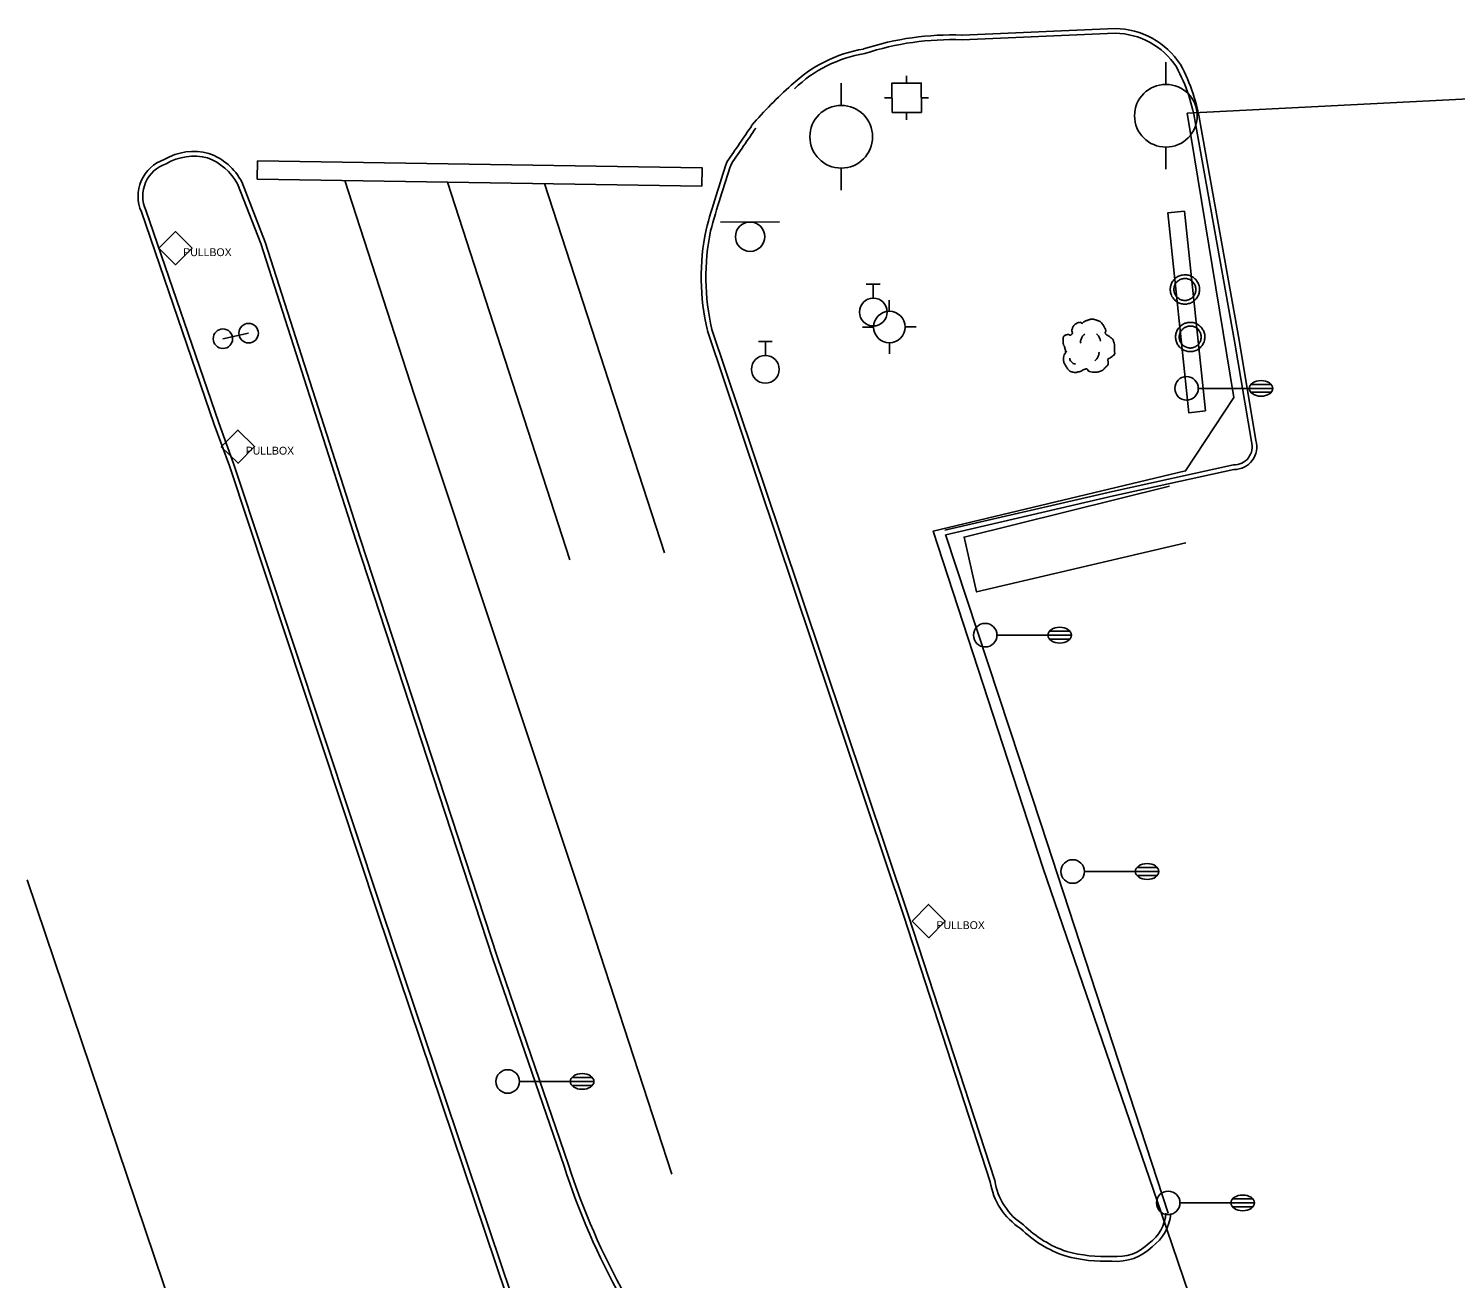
# Model space of a CAD drawing. Extents: x 2145380 to 2156929, y 139568 to 149130.
# Drawn here: x 2147379.3 to 2147561.3, y 142759 to 142918.4 of the extents above; entities that cross this region are included whole.
import ezdxf

# ---------------------------------------------------------------- set-up
doc = ezdxf.new("R2010")
doc.units = 0
for name, color, linetype in [('Default', 7, 'Continuous'), ('TOPO_Asphalt', 7, 'Continuous'), ('TOPO_Curb Back', 7, 'Continuous'), ('TOPO_Fence', 7, 'Continuous'), ('TOPO_Guardrail', 7, 'Continuous'), ('TOPO_Light Pole', 7, 'Continuous'), ('TOPO_Misc', 7, 'Continuous'), ('TOPO_Misc Line', 7, 'Continuous'), ('TOPO_Power Pole', 7, 'Continuous'), ('TOPO_Power Pullbox', 7, 'Continuous'), ('TOPO_Sign', 7, 'Continuous'), ('TOPO_Traffic Signal', 7, 'Continuous'), ('TOPO_Tree', 7, 'Continuous'), ('TOPO_Wall Freestanding', 7, 'Continuous'), ('TOPO_Water Fire Hydrant', 7, 'Continuous'), ('TOPO_Water Valve', 7, 'Continuous')]:
    doc.layers.add(name, color=color, linetype=linetype)

# ---------------------------------------------------------------- blocks, each defined once
blk = doc.blocks.new('POST')
at = {"layer": 'TOPO_Misc'}
for start, end in [(90, 180), (180, 270), (360, 90), (270, 0)]:
    blk.add_arc((-0.01, 0.03), 3.16, start, end, dxfattribs=at)
blk = doc.blocks.new('LP')
at = {"layer": 'TOPO_Light Pole'}
blk.add_line((3.81, 0), (20.32, 0), dxfattribs=at)
for points in [[(20.32, 0), (27.94, 0)], [(20.32, 0), (23.5, 0)], [(20.83, 1.27), (27.43, 1.27)], [(20.83, 1.27), (23.5, 1.27)], [(23.71, 1.27), (27.43, 1.27)], [(23.71, 0), (27.94, 0)], [(20.83, -1.27), (27.43, -1.27)], [(20.83, -1.27), (23.5, -1.27)], [(23.71, -1.27), (27.43, -1.27)]]:
    blk.add_lwpolyline(points, dxfattribs=at)
blk.add_circle((0, 0), 3.81, dxfattribs=at)
blk.add_ellipse((24.13, 0), major_axis=(3.81, 0), ratio=0.666667, dxfattribs=at)
blk = doc.blocks.new('FIRHYD')
at = {"layer": 'TOPO_Water Fire Hydrant'}
for p, q in [((-0.02, 10.16), (-0.03, 17.34)), ((10.16, 0.02), (17.34, 0.03)), ((-10.16, -0.02), (-17.34, -0.03)), ((0.02, -10.16), (0.03, -17.34))]:
    blk.add_line(p, q, dxfattribs=at)
blk.add_circle((0, 0), 10.16, dxfattribs=at)
blk = doc.blocks.new('TRFSIG')
at = {"layer": 'TOPO_Traffic Signal'}
for p, q in [((0.04, 4.66), (0.04, 7.04)), ((-4.7, -0.09), (-7.08, -0.09)), ((4.79, -0.09), (7.17, -0.09)), ((0.04, -4.83), (0.04, -7.22))]:
    blk.add_line(p, q, dxfattribs=at)
blk.add_lwpolyline([(-4.7, -4.85), (4.81, -4.83), (4.79, 4.67), (-4.72, 4.66), (-4.7, -4.85)], dxfattribs=at)
blk = doc.blocks.new('TREE')
at = {"layer": 'TOPO_Tree'}
for points in [[(-14.07, -0.4), (-14.17, 0.5), (-14.37, 1.38), (-14.6, 2.25), (-14.84, 3.17), (-15.47, 3.96), (-15.66, 4.9), (-15.8, 5.59), (-15.71, 6.31), (-15.66, 7.01), (-15.6, 7.91), (-15.72, 8.8), (-15.13, 9.66), (-14.62, 10.42), (-13.76, 10.49), (-13.02, 10.72), (-12.18, 10.98), (-11.06, 10), (-10.37, 10.72), (-9.4, 11.74), (-10.29, 13.28), (-9.84, 14.42), (-9.56, 15.15), (-9.32, 15.89), (-8.78, 16.54), (-8.18, 17.26), (-7.5, 17.68), (-6.67, 18.13), (-6.14, 18.41), (-5.61, 18.61), (-5.08, 18.66), (-4.55, 18.71), (-4.02, 18.54), (-3.49, 18.13)], [(-3.49, 17.6), (-3.07, 18.27), (-2.58, 18.8), (-1.9, 19.19), (-1.05, 19.68), (-0.19, 19.96), (0.74, 20.24), (1.62, 20.51), (2.51, 20.82), (3.39, 20.77), (4.1, 20.73), (4.8, 20.47), (5.51, 20.24), (6.43, 19.95), (7.32, 19.73), (8.15, 19.19), (9.36, 18.4), (10.02, 17.21), (10.8, 16.01), (11.24, 15.33), (11.58, 14.62), (11.86, 13.89), (12.17, 13.08), (11.37, 12.02), (11.86, 11.25), (12, 11.03), (12.18, 10.86), (12.39, 10.72), (12.91, 10.35), (13.45, 10.02), (13.97, 9.66), (14.7, 9.16), (15.41, 8.68), (16.09, 8.07), (16.7, 7.53), (16.93, 6.73), (17.15, 5.95), (17.59, 4.38), (17.71, 2.77), (17.68, 1.19), (17.65, -0.25), (17.83, -2.22), (16.62, -3.04), (15.47, -3.83), (14.31, -4.58), (13.16, -5.35)], [(-4.21, 5.09), (-4.46, 6.09), (-4.3, 7.21), (-3.84, 8.21), (-3.33, 9.34), (-2.71, 10.27), (-1.64, 10.97)], [(5.89, 11.15), (6.5, 10.68), (6.96, 10.17), (7.36, 9.5), (7.93, 8.56), (8.31, 7.6), (8.46, 6.56)], [(13.16, -5.34), (13.25, -5.81), (13.36, -6.28), (13.45, -6.75), (13.76, -8.52), (12.24, -10.03), (10.8, -11.51), (9.98, -12.34), (9.13, -12.77), (8.15, -13.1), (5.97, -13.83), (3.32, -13.56), (1.27, -13.1), (0.49, -12.92), (-0.06, -11.44), (-0.84, -11.51), (-2.04, -11.61), (-3.28, -12.78), (-4.55, -13.1), (-6.06, -13.47), (-7.77, -14.03), (-9.31, -13.62), (-11.36, -13.09), (-12.84, -11.41), (-14.07, -9.39), (-15.32, -7.35), (-15.61, -5.13), (-15.13, -3.04), (-14.87, -1.89), (-13.91, -0.75), (-13.54, 0.13)], [(-11.38, -4.46), (-11.47, -5.41), (-11.03, -6.32), (-10.09, -7.22), (-9.3, -7.97), (-8.49, -8.26), (-7.7, -8.14)], [(4.79, -6.29), (5.71, -5.66), (6.3, -4.92), (6.81, -3.91), (7.36, -2.81), (7.63, -1.7), (7.54, -0.6)]]:
    blk.add_open_spline(points, degree=3, dxfattribs=at)
blk = doc.blocks.new('pulbox')
at = {"layer": 'Default'}
blk.add_lwpolyline([(-5.38, -0.01), (-0.02, 5.42), (5.4, 0.06), (0.05, -5.36), (-5.38, -0.01)], dxfattribs=at)
blk.add_text('PULLBOX', height=2.54, dxfattribs=at).set_placement((2.54, -2.54))
blk = doc.blocks.new('POWPOL')
at = {"layer": 'TOPO_Power Pole'}
for p, q in [((0, 10.16), (0, 17.34)), ((0, -10.16), (0, -17.34))]:
    blk.add_line(p, q, dxfattribs=at)
blk.add_circle((0, 0), 10.16, dxfattribs=at)
blk = doc.blocks.new('WATVAL')
at = {"layer": 'Default'}
for p, q in [((-2.25, 9), (2.25, 9)), ((0, 4.5), (0, 9))]:
    blk.add_line(p, q, dxfattribs=at)
blk.add_circle((0, 0), 4.5, dxfattribs=at)

msp = doc.modelspace()

# ---------------------------------------------------------------- linework, layer by layer
at = {"layer": 'TOPO_Asphalt'}
msp.add_line((2147379.12, 142809.78), (2147402.56, 142740.4), dxfattribs=at)
msp.add_lwpolyline([(2147496.3, 142853.83), (2147508.5, 142816.84), (2147524.71, 142767.27)], dxfattribs=at)
msp.add_arc((2147509.82, 142873.43), 50.24, 131.3733, 139.5513, dxfattribs=at)
at = {"layer": 'TOPO_Curb Back'}
for points in [[(2147498.39, 142917.52), (2147517.93, 142918.36)], [(2147498.39, 142916.92), (2147517.94, 142917.76)], [(2147528.21, 142905.99), (2147533.14, 142878.51), (2147535.31, 142865.7)], [(2147528.81, 142906.09), (2147533.73, 142878.61), (2147535.89, 142865.84)], [(2147405.97, 142898.56), (2147408.92, 142890.94), (2147421.05, 142853.12), (2147438.54, 142799.71), (2147447.62, 142773.28)], [(2147406.51, 142898.82), (2147409.49, 142891.14), (2147421.62, 142853.31), (2147439.11, 142799.9), (2147448.19, 142773.47)], [(2147459.61, 142697.37), (2147440.29, 142756.78), (2147423.84, 142805.62), (2147404.95, 142862.58), (2147403, 142867.87), (2147393.71, 142894.97)], [(2147460.18, 142697.55), (2147440.86, 142756.97), (2147424.41, 142805.81), (2147405.51, 142862.78), (2147403.56, 142868.07), (2147394.27, 142895.2)], [(2147501.98, 142771.3), (2147490.97, 142805.16), (2147474.68, 142853.73), (2147465.91, 142879.83)], [(2147502.56, 142771.44), (2147491.54, 142805.34), (2147475.25, 142853.92), (2147466.49, 142880)], [(2147533.02, 142862.74), (2147517.6, 142859.34), (2147496.18, 142854.4)], [(2147533.08, 142862.14), (2147517.73, 142858.75), (2147496.31, 142853.81)]]:
    msp.add_lwpolyline(points, dxfattribs=at)
for centre, radius, start, end in [((2147497.1, 142881.19), 36.36, 87.9692, 108.0515), ((2147497.1, 142881.19), 35.76, 87.9317, 108.1243), ((2147517.85, 142908.37), 9.99, 32.7044, 89.5788), ((2147517.85, 142908.37), 9.39, 32.8416, 89.4881), ((2147488.7, 142898.54), 17.45, 99.439, 133.8316), ((2147488.7, 142898.54), 16.85, 99.2861, 133.8316), ((2147505.88, 142902.76), 22.57, 8.2439, 28.3156), ((2147505.88, 142902.76), 23.17, 8.2689, 28.3737), ((2146881.44, 143306.93), 713.45, 325.36065, 325.80896), ((2146881.44, 143306.93), 714.05, 325.36729, 325.80896), ((2147400.38, 142895.27), 7.42, 74.9444, 120.5515), ((2147399.61, 142895.05), 7.87, 28.6108, 69.8923), ((2147398.21, 142896.99), 4.94, 108.9166, 204.1165), ((2147398.21, 142896.99), 4.34, 108.1176, 204.4649), ((2147400.38, 142895.27), 6.82, 75.1665, 121.0713), ((2147399.61, 142895.05), 7.27, 28.9113, 69.6834), ((2147608.42, 142853.33), 148.02, 161.0505, 164.5766), ((2147608.42, 142853.33), 147.42, 161.0826, 164.5689), ((2147495.03, 142886.66), 29.91, 168.3561, 193.1887), ((2147495.03, 142886.66), 29.31, 168.3946, 193.1338), ((2147533.12, 142865.02), 2.89, 269.0909, 16.3686), ((2147533.12, 142865.02), 2.29, 267.4345, 17.2036), ((2147535.4, 142801.47), 92.2, 197.8061, 209.1932), ((2147535.4, 142801.47), 91.6, 197.8023, 209.2021), ((2147510.72, 142772.73), 8.86, 189.331, 236.8), ((2147510.72, 142772.73), 8.26, 189.0201, 237.2141), ((2147516.23, 142775.81), 14.14, 225.12, 251.5083), ((2147519.18, 142767.71), 5.25, 305.8611, 355.4185), ((2147519.18, 142767.71), 5.85, 306.3459, 355.4185), ((2147516.23, 142775.81), 14.74, 225.3652, 251.5748), ((2147516.65, 142780.44), 18.69, 254.7663, 272.7719), ((2147518.14, 142767.53), 6.39, 264.5901, 314.8334), ((2147518.14, 142767.53), 5.79, 264.1792, 315.2752), ((2147516.65, 142780.44), 19.29, 254.7158, 272.6403)]:
    msp.add_arc(centre, radius, start, end, dxfattribs=at)
at = {"layer": 'TOPO_Fence'}
for p, q in [((2147527.12, 142907.58), (2147564.71, 142909.47)), ((2147537.08, 142728.5), (2147523.83, 142767.24))]:
    msp.add_line(p, q, dxfattribs=at)
at = {"layer": 'TOPO_Guardrail'}
msp.add_lwpolyline([(2147523.83, 142767.24), (2147508.72, 142811.35), (2147494.73, 142854.27), (2147526.91, 142861.94), (2147533.09, 142871.32), (2147527.13, 142907.57)], dxfattribs=at)
at = {"layer": 'TOPO_Misc Line'}
for p, q in [((2147432.75, 142898.78), (2147448.36, 142850.61)), ((2147445.13, 142898.59), (2147460.42, 142851.48))]:
    msp.add_line(p, q, dxfattribs=at)
msp.add_lwpolyline([(2147408.51, 142901.5), (2147465.23, 142900.61), (2147465.19, 142898.27), (2147408.47, 142899.16)], close=True, dxfattribs=at)
msp.add_lwpolyline([(2147419.65, 142898.98), (2147428.48, 142871.71), (2147450.39, 142805.93), (2147461.38, 142772.28)], dxfattribs=at)
at = {"layer": 'TOPO_Power Pole'}
for points in [[(2147524.95, 142885.09), (2147524.95, 142885.22), (2147524.97, 142885.35), (2147524.99, 142885.47), (2147525.03, 142885.6), (2147525.07, 142885.73), (2147525.12, 142885.85), (2147525.18, 142885.97), (2147525.24, 142886.09), (2147525.32, 142886.2), (2147525.4, 142886.3), (2147525.49, 142886.4), (2147525.59, 142886.49), (2147525.69, 142886.57), (2147525.8, 142886.65), (2147525.91, 142886.72), (2147526.03, 142886.78), (2147526.15, 142886.83), (2147526.27, 142886.87), (2147526.4, 142886.91), (2147526.54, 142886.93), (2147526.67, 142886.95), (2147526.8, 142886.95), (2147526.93, 142886.95), (2147527.06, 142886.94), (2147527.19, 142886.92), (2147527.31, 142886.89), (2147527.44, 142886.85), (2147527.56, 142886.8), (2147527.69, 142886.75), (2147527.8, 142886.68), (2147527.91, 142886.61), (2147528.02, 142886.53), (2147528.11, 142886.44), (2147528.21, 142886.35), (2147528.29, 142886.24), (2147528.37, 142886.13), (2147528.44, 142886.02), (2147528.51, 142885.91), (2147528.56, 142885.78), (2147528.6, 142885.66), (2147528.64, 142885.53), (2147528.67, 142885.4), (2147528.68, 142885.27), (2147528.69, 142885.14), (2147528.69, 142885.01), (2147528.68, 142884.88), (2147528.66, 142884.75), (2147528.63, 142884.62), (2147528.59, 142884.49), (2147528.55, 142884.37), (2147528.49, 142884.25), (2147528.44, 142884.13), (2147528.36, 142884.02), (2147528.28, 142883.91), (2147528.19, 142883.81), (2147528.1, 142883.72), (2147528, 142883.64), (2147527.89, 142883.55), (2147527.78, 142883.48), (2147527.67, 142883.42), (2147527.55, 142883.36), (2147527.42, 142883.31), (2147527.29, 142883.28), (2147527.17, 142883.25), (2147527.04, 142883.23), (2147526.9, 142883.22), (2147526.78, 142883.22), (2147526.65, 142883.23), (2147526.52, 142883.24), (2147526.38, 142883.27), (2147526.26, 142883.3), (2147526.14, 142883.35), (2147526.01, 142883.4), (2147525.89, 142883.47), (2147525.78, 142883.53), (2147525.67, 142883.61), (2147525.57, 142883.7), (2147525.48, 142883.79), (2147525.39, 142883.89), (2147525.31, 142884), (2147525.23, 142884.1), (2147525.17, 142884.21), (2147525.11, 142884.34), (2147525.06, 142884.46), (2147525.02, 142884.59), (2147524.99, 142884.71), (2147524.97, 142884.85), (2147524.95, 142884.98), (2147524.95, 142885.09)], [(2147525.42, 142885.09), (2147525.42, 142885.2), (2147525.44, 142885.31), (2147525.46, 142885.42), (2147525.5, 142885.53), (2147525.54, 142885.64), (2147525.59, 142885.75), (2147525.64, 142885.84), (2147525.71, 142885.94), (2147525.78, 142886.02), (2147525.86, 142886.1), (2147525.95, 142886.19), (2147526.05, 142886.25), (2147526.14, 142886.31), (2147526.24, 142886.36), (2147526.35, 142886.4), (2147526.46, 142886.44), (2147526.57, 142886.46), (2147526.68, 142886.49), (2147526.8, 142886.49), (2147526.91, 142886.49), (2147527.02, 142886.48), (2147527.14, 142886.45), (2147527.25, 142886.42), (2147527.35, 142886.38), (2147527.46, 142886.34), (2147527.55, 142886.28), (2147527.65, 142886.21), (2147527.74, 142886.14), (2147527.83, 142886.07), (2147527.9, 142885.98), (2147527.97, 142885.88), (2147528.03, 142885.79), (2147528.09, 142885.69), (2147528.14, 142885.58), (2147528.17, 142885.47), (2147528.2, 142885.36), (2147528.21, 142885.25), (2147528.22, 142885.14), (2147528.22, 142885.03), (2147528.21, 142884.92), (2147528.19, 142884.8), (2147528.17, 142884.69), (2147528.13, 142884.58), (2147528.08, 142884.48), (2147528.03, 142884.38), (2147527.97, 142884.28), (2147527.9, 142884.19), (2147527.82, 142884.1), (2147527.74, 142884.02), (2147527.64, 142883.95), (2147527.55, 142883.89), (2147527.45, 142883.83), (2147527.34, 142883.78), (2147527.24, 142883.75), (2147527.12, 142883.72), (2147527.01, 142883.7), (2147526.89, 142883.69), (2147526.79, 142883.69), (2147526.68, 142883.7), (2147526.57, 142883.71), (2147526.45, 142883.73), (2147526.34, 142883.77), (2147526.24, 142883.81), (2147526.14, 142883.86), (2147526.04, 142883.93), (2147525.94, 142884), (2147525.86, 142884.07), (2147525.78, 142884.15), (2147525.7, 142884.24), (2147525.64, 142884.34), (2147525.59, 142884.43), (2147525.54, 142884.54), (2147525.49, 142884.65), (2147525.46, 142884.76), (2147525.44, 142884.87), (2147525.42, 142884.98), (2147525.42, 142885.09)], [(2147525.63, 142879.02), (2147525.63, 142879.16), (2147525.65, 142879.29), (2147525.67, 142879.41), (2147525.71, 142879.54), (2147525.75, 142879.67), (2147525.8, 142879.79), (2147525.86, 142879.91), (2147525.92, 142880.03), (2147526, 142880.14), (2147526.08, 142880.24), (2147526.17, 142880.34), (2147526.27, 142880.43), (2147526.37, 142880.51), (2147526.48, 142880.59), (2147526.59, 142880.66), (2147526.71, 142880.72), (2147526.83, 142880.77), (2147526.95, 142880.81), (2147527.08, 142880.85), (2147527.22, 142880.87), (2147527.35, 142880.89), (2147527.48, 142880.89), (2147527.61, 142880.89), (2147527.74, 142880.88), (2147527.87, 142880.86), (2147527.99, 142880.83), (2147528.12, 142880.79), (2147528.24, 142880.74), (2147528.37, 142880.69), (2147528.48, 142880.62), (2147528.59, 142880.55), (2147528.7, 142880.47), (2147528.79, 142880.38), (2147528.89, 142880.28), (2147528.97, 142880.18), (2147529.05, 142880.07), (2147529.12, 142879.96), (2147529.19, 142879.85), (2147529.24, 142879.72), (2147529.28, 142879.6), (2147529.32, 142879.47), (2147529.35, 142879.34), (2147529.36, 142879.21), (2147529.37, 142879.07), (2147529.37, 142878.95), (2147529.36, 142878.82), (2147529.34, 142878.69), (2147529.31, 142878.56), (2147529.27, 142878.43), (2147529.23, 142878.31), (2147529.17, 142878.19), (2147529.12, 142878.07), (2147529.04, 142877.96), (2147528.96, 142877.85), (2147528.87, 142877.75), (2147528.78, 142877.66), (2147528.68, 142877.57), (2147528.57, 142877.49), (2147528.46, 142877.42), (2147528.35, 142877.36), (2147528.23, 142877.3), (2147528.1, 142877.25), (2147527.97, 142877.22), (2147527.85, 142877.19), (2147527.72, 142877.17), (2147527.58, 142877.16), (2147527.46, 142877.16), (2147527.33, 142877.17), (2147527.2, 142877.18), (2147527.06, 142877.21), (2147526.94, 142877.24), (2147526.82, 142877.29), (2147526.69, 142877.34), (2147526.57, 142877.41), (2147526.46, 142877.47), (2147526.35, 142877.55), (2147526.25, 142877.63), (2147526.16, 142877.73), (2147526.07, 142877.82), (2147525.99, 142877.93), (2147525.91, 142878.04), (2147525.85, 142878.15), (2147525.79, 142878.28), (2147525.74, 142878.4), (2147525.7, 142878.53), (2147525.67, 142878.65), (2147525.65, 142878.78), (2147525.63, 142878.92), (2147525.63, 142879.02)], [(2147526.1, 142879.02), (2147526.1, 142879.13), (2147526.12, 142879.25), (2147526.14, 142879.36), (2147526.18, 142879.47), (2147526.22, 142879.58), (2147526.27, 142879.68), (2147526.32, 142879.78), (2147526.39, 142879.87), (2147526.46, 142879.96), (2147526.54, 142880.04), (2147526.63, 142880.12), (2147526.73, 142880.19), (2147526.82, 142880.25), (2147526.92, 142880.3), (2147527.03, 142880.34), (2147527.14, 142880.38), (2147527.25, 142880.4), (2147527.36, 142880.42), (2147527.48, 142880.42), (2147527.59, 142880.42), (2147527.7, 142880.42), (2147527.82, 142880.39), (2147527.93, 142880.36), (2147528.03, 142880.32), (2147528.14, 142880.28), (2147528.23, 142880.22), (2147528.33, 142880.15), (2147528.42, 142880.08), (2147528.51, 142880.01), (2147528.58, 142879.92), (2147528.65, 142879.82), (2147528.71, 142879.73), (2147528.77, 142879.62), (2147528.82, 142879.52), (2147528.85, 142879.41), (2147528.88, 142879.3), (2147528.89, 142879.19), (2147528.9, 142879.07), (2147528.9, 142878.97), (2147528.89, 142878.86), (2147528.87, 142878.74), (2147528.85, 142878.63), (2147528.81, 142878.52), (2147528.76, 142878.42), (2147528.71, 142878.32), (2147528.65, 142878.22), (2147528.58, 142878.12), (2147528.5, 142878.04), (2147528.42, 142877.96), (2147528.32, 142877.89), (2147528.23, 142877.83), (2147528.13, 142877.77), (2147528.02, 142877.72), (2147527.92, 142877.68), (2147527.8, 142877.66), (2147527.69, 142877.63), (2147527.57, 142877.62), (2147527.47, 142877.62), (2147527.36, 142877.63), (2147527.25, 142877.65), (2147527.13, 142877.67), (2147527.02, 142877.71), (2147526.92, 142877.75), (2147526.82, 142877.8), (2147526.72, 142877.87), (2147526.62, 142877.93), (2147526.54, 142878.01), (2147526.46, 142878.09), (2147526.38, 142878.18), (2147526.32, 142878.28), (2147526.27, 142878.37), (2147526.22, 142878.47), (2147526.17, 142878.58), (2147526.14, 142878.7), (2147526.12, 142878.81), (2147526.1, 142878.92), (2147526.1, 142879.02)]]:
    msp.add_lwpolyline(points, dxfattribs=at)
at = {"layer": 'TOPO_Sign'}
msp.add_lwpolyline([(2147529.46, 142869.6), (2147526.77, 142895.07), (2147524.63, 142894.85), (2147527.31, 142869.37)], close=True, dxfattribs=at)
for points in [[(2147467.6, 142893.69), (2147475.09, 142893.7)], [(2147471.35, 142893.69), (2147471.35, 142893.69)], [(2147469.48, 142891.82), (2147469.48, 142891.82)], [(2147473.22, 142891.82), (2147473.22, 142891.82)], [(2147471.35, 142889.96), (2147471.35, 142889.96)], [(2147407.38, 142879.5), (2147404.1, 142878.79)]]:
    msp.add_lwpolyline(points, dxfattribs=at)
for start, end in [(90, 180), (360, 90), (180, 270), (270, 0)]:
    msp.add_arc((2147471.35, 142891.82), 1.87, start, end, dxfattribs=at)
at = {"layer": 'TOPO_Wall Freestanding'}
msp.add_lwpolyline([(2147526.93, 142852.77), (2147500.26, 142846.52), (2147498.66, 142853.51), (2147524.86, 142859.99)], dxfattribs=at)

# ---------------------------------------------------------------- block references
at = {"layer": 'TOPO_Light Pole', "xscale": 0.39370000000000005, "yscale": 0.3937000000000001}
for p in [(2147527.04, 142872.47), (2147501.35, 142841), (2147512.51, 142810.86), (2147440.43, 142784.08), (2147524.7, 142768.6)]:
    msp.add_blockref('LP', p, dxfattribs=at)
at = {"layer": 'TOPO_Misc', "xscale": 0.39370000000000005, "yscale": 0.3937000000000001}
for p in [(2147407.38, 142879.5), (2147404.1, 142878.79)]:
    msp.add_blockref('POST', p, dxfattribs=at)
at = {"layer": 'TOPO_Power Pole', "xscale": 0.39370000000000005, "yscale": 0.3937000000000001}
for p in [(2147524.4, 142907.24), (2147482.98, 142904.56)]:
    msp.add_blockref('POWPOL', p, dxfattribs=at)
at = {"layer": 'TOPO_Power Pullbox', "xscale": 0.39370000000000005, "yscale": 0.3937000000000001}
for p in [(2147398.04, 142890.34), (2147406.01, 142865.03), (2147494.13, 142804.52)]:
    msp.add_blockref('pulbox', p, dxfattribs=at)
at = {"layer": 'TOPO_Traffic Signal', "xscale": 0.39370000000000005, "yscale": 0.3937000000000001}
msp.add_blockref('TRFSIG', (2147491.31, 142909.57), dxfattribs=at)
at = {"layer": 'TOPO_Tree', "xscale": 0.19685000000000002, "yscale": 0.19685000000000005}
msp.add_blockref('TREE', (2147514.38, 142877.22), dxfattribs=at)
at = {"layer": 'TOPO_Water Fire Hydrant', "xscale": 0.19685000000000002, "yscale": 0.19685000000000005}
msp.add_blockref('FIRHYD', (2147489.12, 142880.3), dxfattribs=at)
at = {"layer": 'TOPO_Water Valve', "xscale": 0.39370000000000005, "yscale": 0.3937000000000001}
for p in [(2147487.07, 142882.2), (2147473.3, 142874.9)]:
    msp.add_blockref('WATVAL', p, dxfattribs=at)

doc.saveas('drawing.dxf')
